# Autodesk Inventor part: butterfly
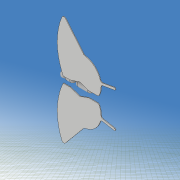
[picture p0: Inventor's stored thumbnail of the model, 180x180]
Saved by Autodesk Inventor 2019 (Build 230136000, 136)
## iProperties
Created: 2021-05
Part Number: butterfly
Material: 一般
Document SubType Name: Modeling
Designer: kikut
Density: 1 g/cm^3
Appearance: 既定
Author: kikut
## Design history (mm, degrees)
sketch "スケッチ1"
  geometry: L1 (80, 60)-(-80, 60); L2 (-80, 60)-(-80, -60); L3 (-80, -60)-(80, -60); L4 (80, -60)-(80, 60); L5 (80, 60)-(-80, -60); L6 (-80, 60)-(80, -60); 1 further point
  constraints: 12 end point, 2 midpoint, 2 parallel, 1 horizontal, 1 perpendicular
  dimensions: "d0" = 160 distance of L2.end L3.end; "d1" = 120 distance of L1.end L2.end
extrude "押し出し1" new body sketch "スケッチ1" stored distance "d2" = 0.6; taper "d3" = 0 deg
sketch "スケッチ2"
  geometry: L1 (-140, 0)-(140, 0) reference; L2 (0, -54)-(20, -30); L3 (0, 54)-(20, 30); L4 (0, -3)-(6.514, -3); L5 (6.514, -3)-(16, -6); L6 (16, -6)-(24, -3); L7 (24, -3)-(33.716, -3); L8 (0, 3)-(6.514, 3); L9 (6.514, 3)-(16, 6); L10 (16, 6)-(24, 3); L11 (24, 3)-(33.716, 3); L12 (0, -98)-(0, 98) reference; L13 (-100, -70)-(100, -70); L14 (100, -70)-(100, 70); L15 (100, 70)-(-100, 70); L16 (-100, 70)-(-100, -70); L17 (-100, -70)-(100, 70); L18 (100, -70)-(-100, 70); A1 r 60 centre (54.312, 28.5) between (0, 54) and (0, 3); A2 r 60 centre (54.312, -28.5) between (0, -3) and (0, -54); A3 r 18.111 centre (18, -12) between (20, -30) and (33.716, -3); A4 r 18.111 centre (18, 12) between (33.716, 3) and (20, 30); 1 further point
  constraints: 32 end point, 8 point on circle, 8 symmetric about line, 4 centre point, 3 horizontal, 2 collinear, 2 midpoint, 2 parallel, 1 perpendicular
  dimensions: "d5" = 60 radius of A1; "d6" = 6 distance of L8.start L4.start; "d7" = 108 distance of L3.start L2.start; "d8" = 0 horizontal distance of L3.start L8.start; "d9" = 60 distance of L3.end L2.end; "d10" = 0 horizontal distance of point (0, 0) L3.start; "d11" = 20 horizontal distance of L3.start L3.end; "d12" = 24 distance of A4.centre A3.centre; "d13" = 6 distance of L11.end L7.end; "d14" = 12 distance of L9.end L5.end; "d15" = 16 distance from line of L12 L5.end; "d16" = 24 distance from line of L6.end L12; "d17" = 200 distance of L14.end L15.end; "d18" = 140 distance of L15.end L13.start; "d30" = 18 distance from line of L12 A4.centre
extrude "押し出し2" cut sketch "スケッチ2" stored distance "d19" = 10; taper "d20" = 0 deg
sketch "スケッチ3"
  geometry: L1 (49.705, -17.97)-(33.948, -15.191); L2 (33.948, -15.191)-(34.295, -13.222); L3 (34.295, -13.222)-(50.052, -16); L4 (50.052, -16)-(49.705, -17.97); L5 (49.705, -17.97)-(34.295, -13.222); L6 (33.948, -15.191)-(50.052, -16); L7 (50.052, 16)-(34.295, 13.222); L8 (34.295, 13.222)-(33.948, 15.191); L9 (33.948, 15.191)-(49.705, 17.97); L10 (49.705, 17.97)-(50.052, 16); L11 (50.052, 16)-(33.948, 15.191); L12 (34.295, 13.222)-(49.705, 17.97); L13 (-112, 0)-(112, 0) reference; L14 (0, -84)-(0, 84) reference; 3 further points
  constraints: 24 end point, 4 midpoint, 4 parallel, 2 perpendicular, 2 symmetric about line
  dimensions: "d21" = 2 distance of L3.end L1.start; "d22" = 2 distance of L9.end L7.start; "d23" = 16 distance of L8.end L9.end; "d24" = 42 distance from line of L14 point (42, 15.596); "d26" = 10 deg angle of L7 L13; "d62" = 16 distance from line of L3.end L13
extrude "押し出し3" join sketch "スケッチ3" distance "d27" = 0.6; taper "d28" = 0 deg
fillet "フィレット1" dims "d31" = 2
fillet "フィレット2" dims "d32" = 1
sketch "スケッチ4"
  geometry: L1 (7, -5)-(1, -5); L2 (19.604, 0)-(-61.477, 0) reference; L3 (0, -10.86)-(0, 2.16) reference; L4 (-19.5, 0.3)-(-2.073, 0.3) reference; L5 (3, -5)-(-7, -5); L6 (0, -8)-(-4, -8); L7 (-5.09, 6.534)-(-4.607, 25.024); A1 r 3 centre (4, -5) between (1, -5) and (7, -5); A2 r 3 centre (0, -5) between (0, -8) and (3, -5); A3 r 3 centre (-4, -5) between (-7, -5) and (-4, -8); 1 further point
  constraints: 8 end point, 6 point on circle, 3 centre point, 2 horizontal, 2 point on line
  dimensions: "d33" = 5 distance between parallel lines of L1 L2; "d34" = 0 vertical distance of L1.start A1.centre; "d35" = 3 radius of A1; "d36" = 1 distance from line of L3 L1.end; "d45" = 0 vertical distance of L6.end L6.start; "d46" = 3 radius of A2; "d47" = 0 distance between parallel lines of L5 L1; "d48" = 4 distance of A1.centre A2.centre; "d49" = 0 horizontal distance of A3.centre L6.end; "d50" = 4 distance of L6.start L6.end
revolve "回転1" sketch "スケッチ4" stored, may be unused: angle "d51" = 90 deg
sketch "スケッチ5"
  geometry: L1 (-8, -5)-(-24, -5); L2 (-11, -8)-(-21, -8); L3 (21.979, 0)-(-61.872, 0) reference; L4 (0, -13.303)-(0, 2.567) reference; A1 r 3 centre (-11, -5) between (-11, -8) and (-8, -5); A2 r 3 centre (-21, -5) between (-24, -5) and (-21, -8); 1 further point
  constraints: 4 end point, 4 point on circle, 2 centre point, 1 horizontal
  dimensions: "d52" = 5 distance between parallel lines of L3 L1; "d53" = 3 radius of A1; "d54" = 3 radius of A2; "d55" = 0 distance from line of L1 A1.centre; "d56" = 0 distance from line of L1 A2.centre; "d57" = 10 distance of L2.start L2.end; "d58" = 90 deg dimension on A1.centre L2.start L1.start; "d59" = 90 deg dimension on A2.centre L1.end L2.end; "d60" = 8 distance from line of L1.start L4
revolve "回転2" sketch "スケッチ5" stored, may be unused: angle "d61" = 90 deg
node "ソリッド1"
